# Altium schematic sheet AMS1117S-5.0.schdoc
size 127 x 101 mm
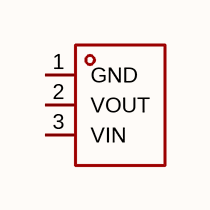
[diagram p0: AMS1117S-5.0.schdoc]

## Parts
U?  ams1117s-5.0  [SOT-89-3_L4.5-W2.5-P1.50-LS4.2-BR]  (value not drawn)

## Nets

Not connected (* = marked no-connect by the designer): U? 1(GND) 2(VOUT) 3(VIN)

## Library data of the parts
U? = ams1117s-5.0: 输出极性:正极;工作电压:30V;输出电压:5V;输出电流:1A;电源纹波抑制比(PSRR):70dB@(120Hz);输出类型:固定;; Manufacturer: JSMSEMI(杰盛微); AddInBom: yes; ModelId: 6db690b7897d4d18a30d90c1b89525ee; ModelName: SOT-89-3_L4.3-W2.5-H1.6-LS4.1-P1.50; ModelTransform: 161.417,169.291,0,180,0,0,-18.661,0,0; Output Configuration: 正极; Voltage - Supply: 30V; Output Voltage: 5V; Output Current: 1A; standby current: 3mA; Noise: 0.003%Vout; Output Type: 固定; Number of Outputs: 1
